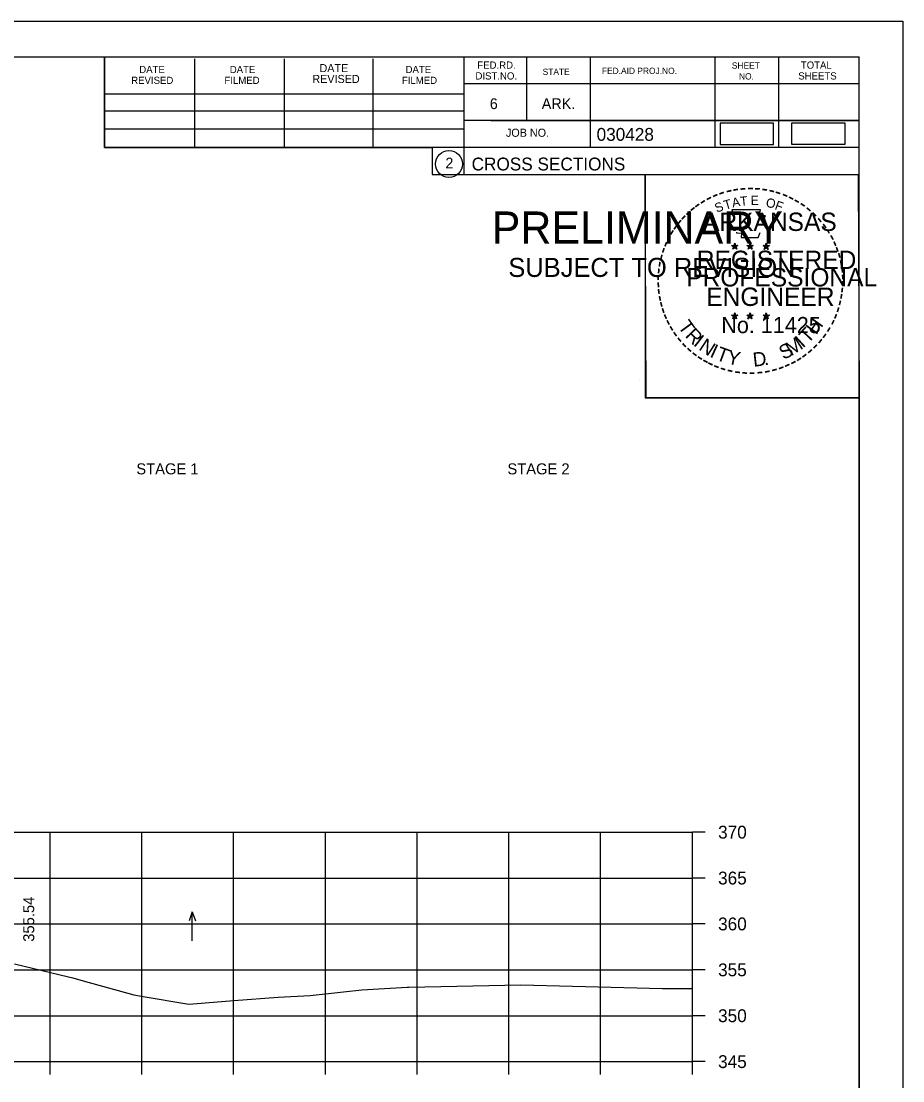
# Model space of a CAD drawing. Extents: x 1374859 to 1376773, y 382242 to 389804.
# Drawn here: x 1376201.4 to 1376297.5, y 386819.7 to 386935.2 of the extents above; entities that cross this region are included whole.
import ezdxf

# ---------------------------------------------------------------- set-up
doc = ezdxf.new("R2010")
doc.units = 0
for name, color, linetype in [('R_Axis', 7, 'Continuous'), ('R_Axis Annot', 7, 'Continuous'), ('R_Border', 7, 'Continuous'), ('R_Border PE', 7, 'Continuous'), ('R_Border Prem', 7, 'Continuous'), ('R_Drive', 7, 'Continuous'), ('R_Exist Surface', 7, 'Continuous'), ('R_Grid', 7, 'Continuous'), ('R_MOT', 7, 'Continuous'), ('R_No Plot', 7, 'Continuous'), ('R_Water Annot', 7, 'Continuous'), ('R_Xsect Elev', 7, 'Continuous')]:
    doc.layers.add(name, color=color, linetype=linetype)

msp = doc.modelspace()

# ---------------------------------------------------------------- linework, layer by layer
at = {"layer": 'R_Axis'}
for p, q in [((1376274.57, 386821.82), (1376274.57, 386846.82)), ((1376275.97, 386846.82), (1376274.57, 386846.82)), ((1376275.97, 386841.82), (1376274.57, 386841.82)), ((1376275.97, 386836.82), (1376274.57, 386836.82)), ((1376275.97, 386831.82), (1376274.57, 386831.82)), ((1376275.97, 386826.82), (1376274.57, 386826.82)), ((1375994.57, 386821.82), (1376274.57, 386821.82)), ((1376204.57, 386820.42), (1376204.57, 386821.82)), ((1376214.57, 386820.42), (1376214.57, 386821.82)), ((1376224.57, 386820.42), (1376224.57, 386821.82)), ((1376234.57, 386820.42), (1376234.57, 386821.82)), ((1376244.57, 386820.42), (1376244.57, 386821.82)), ((1376254.57, 386820.42), (1376254.57, 386821.82)), ((1376264.57, 386820.42), (1376264.57, 386821.82)), ((1376274.57, 386820.42), (1376274.57, 386821.82)), ((1376275.97, 386821.82), (1376274.57, 386821.82))]:
    msp.add_line(p, q, dxfattribs=at)
at = {"layer": 'R_Border'}
for p, q in [((1375976.57, 386931.28), (1376292.75, 386931.28)), ((1376210.49, 386921.4), (1376210.49, 386931.28)), ((1376220.35, 386921.4), (1376220.35, 386931.08)), ((1376230.11, 386921.4), (1376230.11, 386931.08)), ((1376239.79, 386921.4), (1376239.79, 386931.08)), ((1376249.65, 386931.28), (1376249.65, 386918.48)), ((1376256.49, 386931.28), (1376256.49, 386924.34)), ((1376263.43, 386931.28), (1376263.43, 386921.4)), ((1376277.01, 386931.28), (1376277.01, 386921.4)), ((1376283.95, 386931.28), (1376283.95, 386921.4)), ((1376292.75, 386725.82), (1376292.75, 386931.28)), ((1376292.75, 386928.34), (1376249.65, 386928.34)), ((1376292.75, 386928.36), (1376292.75, 386928.36)), ((1376210.49, 386927.26), (1376249.65, 386927.26)), ((1376210.49, 386925.4), (1376249.65, 386925.4)), ((1376292.75, 386924.34), (1376249.65, 386924.34)), ((1376252.61, 386924.34), (1376292.75, 386924.34)), ((1376210.49, 386921.4), (1376210.49, 386923.46)), ((1376210.49, 386923.46), (1376249.65, 386923.46)), ((1376292.75, 386921.4), (1376210.49, 386921.4)), ((1376249.65, 386918.48), (1376292.75, 386918.48))]:
    msp.add_line(p, q, dxfattribs=at)
msp.add_circle((1376248.04, 386919.61), 1.47, dxfattribs=at)
at = {"layer": 'R_Border PE'}
for p, q in [((1376278.84, 386910.73), (1376279.18, 386910.62)), ((1376278.84, 386910.73), (1376279.09, 386910.69)), ((1376278.84, 386910.73), (1376279.07, 386910.61)), ((1376278.97, 386910.33), (1376279.18, 386910.62)), ((1376278.97, 386910.33), (1376279.09, 386910.57)), ((1376278.97, 386910.33), (1376279.18, 386910.54)), ((1376279.18, 386910.99), (1376279.14, 386910.74)), ((1376279.18, 386910.62), (1376279.18, 386910.99)), ((1376279.18, 386910.99), (1376279.23, 386910.74)), ((1376279.53, 386910.73), (1376279.18, 386910.62)), ((1376279.4, 386910.33), (1376279.18, 386910.62)), ((1376279.4, 386910.33), (1376279.18, 386910.54)), ((1376279.53, 386910.73), (1376279.25, 386910.68)), ((1376279.4, 386910.33), (1376279.26, 386910.62)), ((1376279.53, 386910.73), (1376279.33, 386910.63)), ((1376280.51, 386910.73), (1376280.85, 386910.62)), ((1376280.51, 386910.73), (1376280.76, 386910.69)), ((1376280.51, 386910.73), (1376280.74, 386910.61)), ((1376280.64, 386910.33), (1376280.85, 386910.62)), ((1376280.64, 386910.33), (1376280.76, 386910.57)), ((1376280.64, 386910.33), (1376280.85, 386910.54)), ((1376280.85, 386910.99), (1376280.81, 386910.74)), ((1376280.85, 386910.62), (1376280.85, 386910.99)), ((1376280.85, 386910.99), (1376280.9, 386910.74)), ((1376281.2, 386910.73), (1376280.85, 386910.62)), ((1376281.07, 386910.33), (1376280.85, 386910.62)), ((1376281.07, 386910.33), (1376280.85, 386910.54)), ((1376281.2, 386910.73), (1376280.92, 386910.68)), ((1376281.07, 386910.33), (1376280.93, 386910.62)), ((1376281.2, 386910.73), (1376281, 386910.63)), ((1376282.27, 386910.72), (1376282.62, 386910.61)), ((1376282.27, 386910.72), (1376282.52, 386910.68)), ((1376282.27, 386910.72), (1376282.51, 386910.6)), ((1376282.4, 386910.31), (1376282.62, 386910.61)), ((1376282.4, 386910.31), (1376282.53, 386910.56)), ((1376282.4, 386910.31), (1376282.62, 386910.53)), ((1376282.62, 386910.98), (1376282.58, 386910.72)), ((1376282.62, 386910.61), (1376282.62, 386910.98)), ((1376282.62, 386910.98), (1376282.67, 386910.73)), ((1376282.97, 386910.72), (1376282.62, 386910.61)), ((1376282.83, 386910.31), (1376282.62, 386910.61)), ((1376282.83, 386910.31), (1376282.62, 386910.53)), ((1376282.97, 386910.72), (1376282.68, 386910.67)), ((1376282.83, 386910.31), (1376282.69, 386910.6)), ((1376282.97, 386910.72), (1376282.76, 386910.62)), ((1376279.18, 386903.41), (1376279.14, 386903.16)), ((1376279.18, 386903.05), (1376279.18, 386903.41)), ((1376279.18, 386903.41), (1376279.23, 386903.16)), ((1376280.85, 386903.41), (1376280.81, 386903.16)), ((1376280.85, 386903.05), (1376280.85, 386903.41)), ((1376280.85, 386903.41), (1376280.9, 386903.16)), ((1376282.62, 386903.4), (1376282.58, 386903.15)), ((1376282.62, 386903.04), (1376282.62, 386903.4)), ((1376282.62, 386903.4), (1376282.67, 386903.15)), ((1376278.83, 386903.16), (1376279.18, 386903.05)), ((1376278.83, 386903.16), (1376279.08, 386903.12)), ((1376278.83, 386903.16), (1376279.07, 386903.04)), ((1376278.96, 386902.75), (1376279.18, 386903.05)), ((1376278.96, 386902.75), (1376279.09, 386903)), ((1376278.96, 386902.75), (1376279.18, 386902.97)), ((1376279.53, 386903.16), (1376279.18, 386903.05)), ((1376279.39, 386902.75), (1376279.18, 386903.05)), ((1376279.39, 386902.75), (1376279.18, 386902.97)), ((1376279.53, 386903.16), (1376279.24, 386903.11)), ((1376279.39, 386902.75), (1376279.26, 386903.04)), ((1376279.53, 386903.16), (1376279.32, 386903.06)), ((1376280.5, 386903.16), (1376280.85, 386903.05)), ((1376280.5, 386903.16), (1376280.75, 386903.12)), ((1376280.5, 386903.16), (1376280.74, 386903.04)), ((1376280.63, 386902.75), (1376280.85, 386903.05)), ((1376280.63, 386902.75), (1376280.76, 386903)), ((1376280.63, 386902.75), (1376280.85, 386902.97)), ((1376281.2, 386903.16), (1376280.85, 386903.05)), ((1376281.06, 386902.75), (1376280.85, 386903.05)), ((1376281.06, 386902.75), (1376280.85, 386902.97)), ((1376281.2, 386903.16), (1376280.91, 386903.11)), ((1376281.06, 386902.75), (1376280.93, 386903.04)), ((1376281.2, 386903.16), (1376280.99, 386903.06)), ((1376282.27, 386903.15), (1376282.62, 386903.04)), ((1376282.27, 386903.15), (1376282.52, 386903.11)), ((1376282.27, 386903.15), (1376282.5, 386903.03)), ((1376282.4, 386902.74), (1376282.62, 386903.04)), ((1376282.4, 386902.74), (1376282.53, 386902.99)), ((1376282.4, 386902.74), (1376282.61, 386902.96)), ((1376282.83, 386902.74), (1376282.61, 386902.96)), ((1376282.96, 386903.15), (1376282.62, 386903.04)), ((1376282.83, 386902.74), (1376282.62, 386903.04)), ((1376282.96, 386903.15), (1376282.68, 386903.1)), ((1376282.83, 386902.74), (1376282.69, 386903.03)), ((1376282.96, 386903.15), (1376282.76, 386903.05))]:
    msp.add_line(p, q, dxfattribs=at)
for points in [[(1376278.88, 386914.61), (1376279.15, 386913.78)], [(1376282.39, 386913.69), (1376282.53, 386913.97), (1376281.84, 386913.95), (1376281.99, 386914.61), (1376278.88, 386914.61)], [(1376279.37, 386912.19), (1376279.37, 386912.1), (1376279.93, 386912.08), (1376279.88, 386911.61), (1376281.75, 386911.61), (1376281.95, 386912.15)], [(1376279.18, 386910.99), (1376279.4, 386910.33), (1376278.84, 386910.73), (1376279.53, 386910.73), (1376278.97, 386910.33), (1376279.18, 386910.99)], [(1376280.85, 386910.99), (1376281.07, 386910.33), (1376280.51, 386910.73), (1376281.2, 386910.73), (1376280.64, 386910.33), (1376280.85, 386910.99)], [(1376282.62, 386910.98), (1376282.83, 386910.31), (1376282.27, 386910.72), (1376282.97, 386910.72), (1376282.4, 386910.31), (1376282.62, 386910.98)], [(1376279.18, 386903.41), (1376279.39, 386902.75), (1376278.83, 386903.16), (1376279.53, 386903.16), (1376278.96, 386902.75), (1376279.18, 386903.41)], [(1376280.85, 386903.41), (1376281.06, 386902.75), (1376280.5, 386903.16), (1376281.2, 386903.16), (1376280.63, 386902.75), (1376280.85, 386903.41)], [(1376282.62, 386903.4), (1376282.83, 386902.74), (1376282.27, 386903.15), (1376282.96, 386903.15), (1376282.4, 386902.74), (1376282.62, 386903.4)]]:
    msp.add_lwpolyline(points, dxfattribs=at)
for centre, radius in [((1376279.18, 386910.62), 0.172), ((1376279.18, 386910.62), 0.145), ((1376279.18, 386910.62), 0.116), ((1376279.18, 386910.62), 0.0991), ((1376279.18, 386910.62), 0.0747), ((1376279.18, 386910.62), 0.0495), ((1376279.18, 386910.62), 0.0296), ((1376280.85, 386910.62), 0.172), ((1376280.85, 386910.62), 0.145), ((1376280.85, 386910.62), 0.116), ((1376280.85, 386910.62), 0.0991), ((1376280.85, 386910.62), 0.0747), ((1376280.85, 386910.62), 0.0495), ((1376280.85, 386910.62), 0.0296), ((1376282.62, 386910.61), 0.172), ((1376282.62, 386910.61), 0.145), ((1376282.62, 386910.61), 0.116), ((1376282.62, 386910.61), 0.0991), ((1376282.62, 386910.61), 0.0747), ((1376282.62, 386910.61), 0.0495), ((1376282.62, 386910.61), 0.0296), ((1376279.18, 386903.05), 0.172), ((1376279.18, 386903.05), 0.145), ((1376279.18, 386903.05), 0.116), ((1376279.18, 386903.05), 0.0991), ((1376279.18, 386903.05), 0.0747), ((1376279.18, 386903.05), 0.0495), ((1376279.18, 386903.05), 0.0296), ((1376280.85, 386903.05), 0.172), ((1376280.85, 386903.05), 0.145), ((1376280.85, 386903.05), 0.116), ((1376280.85, 386903.05), 0.0991), ((1376280.85, 386903.05), 0.0747), ((1376280.85, 386903.05), 0.0495), ((1376280.85, 386903.05), 0.0296), ((1376282.62, 386903.04), 0.172), ((1376282.62, 386903.04), 0.145), ((1376282.62, 386903.04), 0.116), ((1376282.62, 386903.04), 0.0991), ((1376282.62, 386903.04), 0.0747), ((1376282.62, 386903.04), 0.0495), ((1376282.62, 386903.04), 0.0296)]:
    msp.add_circle(centre, radius, dxfattribs=at)
at = {"layer": 'R_Drive'}
msp.add_lwpolyline([(1376277.58, 386921.75), (1376283.41, 386921.75), (1376283.41, 386924.06), (1376277.58, 386924.06)], close=True, dxfattribs=at)
at = {"layer": 'R_Exist Surface'}
msp.add_lwpolyline([(1376200.7, 386832.48), (1376206.59, 386831.07), (1376207.04, 386830.95), (1376208.17, 386830.62), (1376213.69, 386829.09), (1376214.72, 386828.93), (1376219.69, 386828.08), (1376224.6, 386828.46), (1376229.43, 386828.85), (1376232.9, 386829.04), (1376236.56, 386829.44), (1376238.54, 386829.64), (1376243.5, 386829.93), (1376243.53, 386829.93), (1376243.68, 386829.93), (1376255.87, 386830.17), (1376261.52, 386830.03), (1376271.31, 386829.8), (1376274.57, 386829.77)], dxfattribs=at)
at = {"layer": 'R_Grid'}
for p, q in [((1375994.57, 386846.82), (1376274.57, 386846.82)), ((1376204.57, 386821.82), (1376204.57, 386846.82)), ((1376214.57, 386821.82), (1376214.57, 386846.82)), ((1376224.57, 386821.82), (1376224.57, 386846.82)), ((1376234.57, 386821.82), (1376234.57, 386846.82)), ((1376244.57, 386821.82), (1376244.57, 386846.82)), ((1376254.57, 386821.82), (1376254.57, 386846.82)), ((1376264.57, 386821.82), (1376264.57, 386846.82)), ((1376274.57, 386821.82), (1376274.57, 386846.82)), ((1375994.57, 386841.82), (1376274.57, 386841.82)), ((1375994.57, 386836.82), (1376274.57, 386836.82)), ((1375994.57, 386831.82), (1376274.57, 386831.82)), ((1375994.57, 386826.82), (1376274.57, 386826.82)), ((1375994.57, 386821.82), (1376274.57, 386821.82))]:
    msp.add_line(p, q, dxfattribs=at)
at = {"layer": 'R_MOT'}
msp.add_lwpolyline([(1376285.38, 386921.76), (1376291.21, 386921.76), (1376291.21, 386924.07), (1376285.38, 386924.07)], close=True, dxfattribs=at)
at = {"layer": 'R_No Plot'}
for p, q in [((1375964.17, 386935.17), (1376297.5, 386935.17)), ((1376268.78, 386896.02), (1376268.78, 386896.02))]:
    msp.add_line(p, q, dxfattribs=at)
for points in [[(1375964.16, 386935.17), (1376297.5, 386935.17), (1376297.5, 386721.84), (1375964.16, 386721.84)], [(1376210.49, 386931.28), (1376210.49, 386921.4), (1376246.22, 386921.4), (1376246.22, 386918.48), (1376269.42, 386918.48), (1376269.42, 386894.15), (1376292.75, 386894.15), (1376292.75, 386725.82), (1375976.57, 386725.82), (1375976.57, 386931.28)], [(1376269.42, 386918.48), (1376292.63, 386918.48), (1376292.75, 386894.15), (1376269.54, 386894.15)]]:
    msp.add_lwpolyline(points, close=True, dxfattribs=at)
at = {"layer": 'R_Water Annot'}
for p, q in [((1376220.07, 386838.14), (1376219.72, 386837.17)), ((1376220.07, 386834.99), (1376220.07, 386838.14)), ((1376220.07, 386838.14), (1376220.42, 386837.17))]:
    msp.add_line(p, q, dxfattribs=at)

# ---------------------------------------------------------------- texts
at = {"layer": 'R_Axis Annot'}
for s, p in [('STAGE 1', (1376213.97, 386885.8)), ('STAGE 2', (1376254.41, 386885.8))]:
    msp.add_text(s, height=1.2, rotation=360, dxfattribs=at).set_placement(p)
for s, p in [('370', (1376277.37, 386846.12)), ('365', (1376277.37, 386841.12)), ('360', (1376277.37, 386836.12)), ('355', (1376277.37, 386831.12)), ('350', (1376277.37, 386826.12)), ('345', (1376277.37, 386821.12))]:
    msp.add_text(s, height=1.4, dxfattribs=at).set_placement(p)
at = {"layer": 'R_Border'}
for s, height, p in [('DATE', 0.782, (1376214.29, 386929.52)), ('DATE', 0.782, (1376224.15, 386929.52)), ('DATE', 0.879, (1376233.93, 386929.62)), ('DATE', 0.782, (1376243.31, 386929.52)), ('FED.RD.', 0.782, (1376251.13, 386930)), ('STATE', 0.684, (1376258.25, 386929.32)), ('FED.AID PROJ.NO.', 0.684, (1376264.71, 386929.42)), ('SHEET', 0.684, (1376278.87, 386930)), ('TOTAL', 0.782, (1376286.39, 386930)), ('REVISED', 0.782, (1376213.41, 386928.34)), ('FILMED', 0.782, (1376223.57, 386928.34)), ('REVISED', 0.879, (1376233.15, 386928.44)), ('FILMED', 0.782, (1376242.91, 386928.34)), ('DIST.NO.', 0.782, (1376250.93, 386928.82)), ('NO.', 0.684, (1376279.65, 386928.82)), ('SHEETS', 0.782, (1376286.11, 386928.82)), ('6', 1.17, (1376252.49, 386925.6)), ('ARK.', 1.172, (1376258.15, 386925.6)), ('JOB NO.', 0.879, (1376254.25, 386922.58)), ('030428', 1.4, (1376264.13, 386922.14)), ('2', 1.17, (1376247.65, 386919.13)), ('CROSS SECTIONS', 1.4, (1376250.51, 386918.91))]:
    msp.add_text(s, height=height, rotation=360, dxfattribs=at).set_placement(p)
at = {"layer": 'R_Border PE'}
for s, height, rotation, p in [('-', 1.6, 28.7918, (1376276.36, 386915.15)), ('-', 1.6, 24.3072, (1376276.99, 386915.47)), ('-', 1.6, 19.1761, (1376277.62, 386915.74)), ('-', 1.6, 13.6301, (1376278.37, 386915.98)), ('A', 1, 11.2132, (1376278.97, 386914.87)), ('-', 1.6, 10.2193, (1376279.05, 386916.14)), ('T', 1, 6.0228, (1376279.82, 386915.04)), ('-', 1.6, 5.8968, (1376279.78, 386916.25)), ('-', 1.6, 0.1862, (1376280.55, 386916.32)), ('E', 1, 0.8323, (1376280.93, 386915.15)), ('-', 1.6, 357.743, (1376281.28, 386916.31)), ('-', 1.6, 352.1617, (1376282.02, 386916.25)), ('-', 1.6, 347.2049, (1376282.74, 386916.14)), ('-', 1.6, 342.3362, (1376283.37, 386915.99)), ('-', 1.6, 337.8551, (1376284.11, 386915.76)), ('-', 1.6, 334.1211, (1376284.74, 386915.49)), ('-', 1.6, 38.9507, (1376274.71, 386914.01)), ('-', 1.6, 36.2317, (1376275.18, 386914.39)), ('-', 1.6, 34.0636, (1376275.76, 386914.78)), ('S', 1, 21.594, (1376277.23, 386914.29)), ('T', 1, 16.4036, (1376278.15, 386914.62)), ('O', 1, 350.4515, (1376282.53, 386914.94)), ('F', 1, 340.0707, (1376283.48, 386914.71)), ('-', 1.6, 329.6409, (1376285.32, 386915.21)), ('-', 1.6, 325.8627, (1376285.96, 386914.85)), ('-', 1.6, 320.5297, (1376286.57, 386914.42)), ('-', 1.6, 48.423, (1376273.83, 386913.11)), ('-', 1.6, 42.9622, (1376274.27, 386913.59)), ('ARKANSAS', 2, 360, (1376275.73, 386912.32)), ('-', 1.6, 315.5786, (1376287.17, 386913.93)), ('-', 1.6, 309.8797, (1376287.74, 386913.38)), ('-', 1.6, 54.2325, (1376273.01, 386912.06)), ('-', 1.6, 50.6142, (1376273.42, 386912.63)), ('-', 1.6, 306.6522, (1376288.27, 386912.78)), ('-', 1.4, 303.6753, (1376288.75, 386912.21)), ('-', 1.6, 62.8713, (1376272.37, 386910.92)), ('-', 1.6, 58.0706, (1376272.68, 386911.53)), ('-', 1.6, 299.6684, (1376289.07, 386911.61)), ('-', 1.6, 72.3945, (1376271.89, 386909.68)), ('-', 1.6, 67.7743, (1376272.11, 386910.31)), ('REGISTERED', 2, 360, (1376275.05, 386908.17)), ('DWB', 0.01, 360, (1376279.17, 386910.62)), ('DWB', 0.01, 360, (1376280.84, 386910.62)), ('DWB', 0.01, 360, (1376282.61, 386910.61)), ('-', 1.6, 294.6628, (1376289.39, 386910.99)), ('-', 1.6, 290.5728, (1376289.65, 386910.42)), ('-', 1.6, 75.461, (1376271.7, 386908.97)), ('-', 1.6, 285.1233, (1376289.89, 386909.84)), ('-', 1.6, 280.5493, (1376290.09, 386909.1)), ('-', 1.6, 85.1863, (1376271.49, 386907.56)), ('-', 1.6, 81.2013, (1376271.56, 386908.25)), ('PROFESSIONAL', 2, 360, (1376273.9, 386906.27)), ('-', 1.6, 276.5962, (1376290.25, 386908.33)), ('-', 1.6, 94.1959, (1376271.5, 386906.14)), ('-', 1.6, 89.0622, (1376271.46, 386906.86)), ('-', 1.6, 274.3301, (1376290.31, 386907.61)), ('-', 1.6, 269.9407, (1376290.34, 386906.97)), ('-', 1.6, 98.9479, (1376271.57, 386905.47)), ('ENGINEER', 2, 360, (1376276.09, 386904.15)), ('-', 1.6, 263.5172, (1376290.32, 386906.31)), ('-', 1.6, 101.7149, (1376271.71, 386904.74)), ('-', 1.6, 105.4578, (1376271.87, 386904.14)), ('-', 1.6, 255.7626, (1376290.14, 386904.98)), ('-', 1.6, 260.9953, (1376290.25, 386905.65)), ('-', 1.6, 109.0874, (1376272.08, 386903.51)), ('-', 1.6, 114.0643, (1376272.34, 386902.91)), ('-', 1.6, 247.8887, (1376289.74, 386903.58)), ('-', 1.6, 252.8681, (1376289.96, 386904.26)), ('-', 1.6, 115.7289, (1376272.64, 386902.3)), ('T', 1.54, 306.0406, (1376272.94, 386901.89)), ('No. 11425', 1.757, 360, (1376277.72, 386901.19)), ('DWB', 0.01, 360, (1376279.17, 386903.04)), ('DWB', 0.01, 360, (1376280.84, 386903.04)), ('DWB', 0.01, 360, (1376282.6, 386903.03)), ('H', 1.54, 54.6088, (1376288.06, 386900.92)), ('-', 1.6, 244.6197, (1376289.48, 386902.95)), ('-', 1.6, 120.4471, (1376273, 386901.71)), ('-', 1.6, 125.8934, (1376273.4, 386901.15)), ('R', 1.54, 314.005, (1376273.7, 386900.84)), ('I', 1.54, 321.9694, (1376274.6, 386899.91)), ('T', 1.54, 46.6444, (1376287.17, 386899.98)), ('-', 1.6, 233.8452, (1376288.68, 386901.55)), ('-', 1.6, 239.0712, (1376289.08, 386902.2)), ('-', 1.6, 130.7181, (1376273.86, 386900.6)), ('-', 1.6, 134.2238, (1376274.38, 386900.05)), ('N', 1.54, 326.5002, (1376275.17, 386899.44)), ('I', 1.54, 335.3603, (1376276.38, 386898.65)), ('S', 1.54, 26.9312, (1376284.49, 386898.25)), ('M', 1.54, 32.6563, (1376285.32, 386898.65)), ('I', 1.54, 42.1136, (1376286.61, 386899.5)), ('-', 1.6, 225.7653, (1376287.77, 386900.42)), ('-', 1.6, 231.2538, (1376288.25, 386900.98)), ('-', 1.6, 138.9338, (1376274.91, 386899.59)), ('-', 1.6, 144.6463, (1376275.46, 386899.18)), ('-', 1.6, 148.0898, (1376276.02, 386898.81)), ('T', 1.54, 339.8912, (1376277.04, 386898.32)), ('Y', 1.54, 347.8556, (1376278.26, 386897.88)), ('D', 1.54, 6.3969, (1376281.24, 386897.52)), ('-', 1.6, 215.7363, (1376286.7, 386899.44)), ('-', 1.6, 221.0851, (1376287.25, 386899.91)), ('-', 1.6, 151.5704, (1376276.6, 386898.49)), ('-', 1.6, 154.6002, (1376277.12, 386898.24)), ('-', 1.6, 158.5612, (1376277.75, 386897.98)), ('.', 1.54, 13.7642, (1376282.43, 386897.65)), ('-', 1.6, 200.7184, (1376284.36, 386898.11)), ('-', 1.6, 204.2516, (1376284.98, 386898.39)), ('-', 1.6, 207.3568, (1376285.61, 386898.7)), ('-', 1.6, 212.2491, (1376286.17, 386899.05)), ('-', 1.6, 162.7983, (1376278.43, 386897.77)), ('-', 1.6, 167.5555, (1376279.15, 386897.61)), ('-', 1.6, 173.1155, (1376279.92, 386897.5)), ('-', 1.6, 176.5183, (1376280.67, 386897.44)), ('-', 1.6, 181.5918, (1376281.41, 386897.46)), ('-', 1.6, 185.8167, (1376282.22, 386897.54)), ('-', 1.6, 191.2858, (1376282.96, 386897.67)), ('-', 1.6, 195.4743, (1376283.69, 386897.87))]:
    msp.add_text(s, height=height, rotation=rotation, dxfattribs=at).set_placement(p)
at = {"layer": 'R_Border Prem'}
for s, height, p in [('PRELIMINARY', 3.5, (1376252.7, 386910.94)), ('DWB', 0.01, (1376253.45, 386912.79)), ('SUBJECT TO REVISION', 2.0751, (1376254.51, 386907.31))]:
    msp.add_text(s, height=height, rotation=360, dxfattribs=at).set_placement(p)
at = {"layer": 'R_Xsect Elev'}
msp.add_text('355.54', height=1.2, rotation=90, dxfattribs=at).set_placement((1376202.84, 386834.88))

doc.saveas('drawing.dxf')
